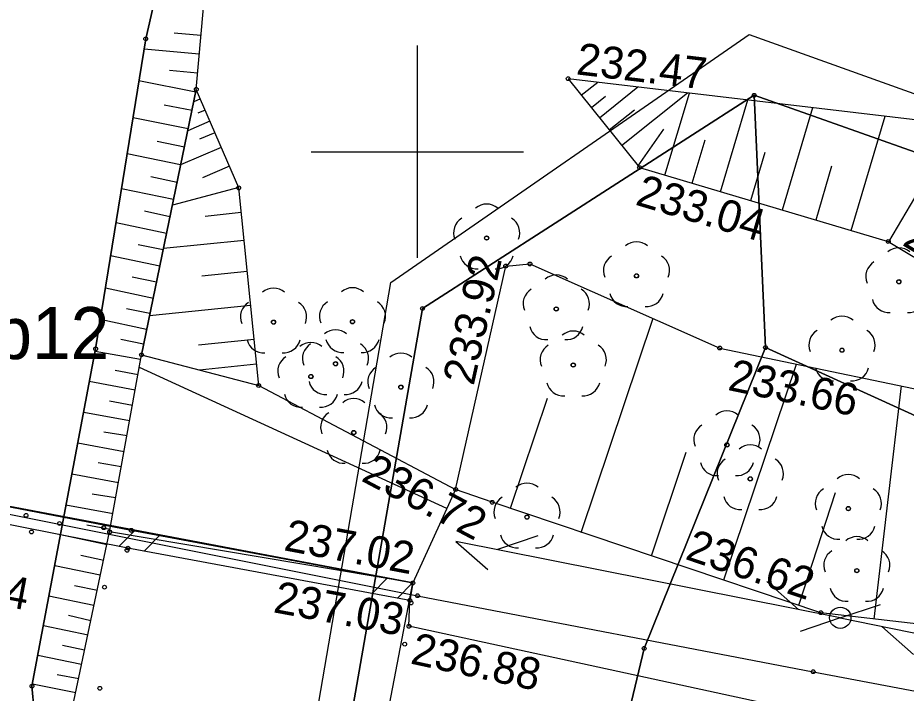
# Model space of a CAD drawing. Extents: x 6596400 to 6597200, y 5539751 to 5540251.
# Drawn here: x 6596740.59 to 6596761.51, y 5540088.25 to 5540104.16 of the extents above; entities that cross this region are included whole.
import ezdxf

# ---------------------------------------------------------------- set-up
doc = ezdxf.new("R2010")
doc.units = 0
for name, color, linetype in [('000 Inne (niezydentyfikowane)', 7, 'Continuous'), ('140-Punkty robocze', 7, 'Continuous'), ('203-punkt graniczny', 7, 'Continuous'), ('217-kontur klasyfikacyjny', 7, 'Continuous'), ('218-kontur użytku gruntowego', 7, 'Continuous'), ('219-działka ewidencyjna', 7, 'Continuous'), ('bariera ochronna', 7, 'Continuous'), ('drzewo liściaste', 7, 'Continuous'), ('jezdnia', 7, 'Continuous'), ('Linia obszaru zagospodarowania terenu', 7, 'Continuous'), ('most', 7, 'Continuous'), ('Opis obszaru zagospodarowania terenu', 7, 'Continuous'), ('pikieta sztuczna', 7, 'Continuous'), ('pikieta sztuczna-Atr2', 7, 'Continuous'), ('przewód telekomunikacyjny napowietrzny', 7, 'Continuous'), ('skarpa nieumocniona', 7, 'Continuous'), ('skarpa umocniona', 7, 'Continuous'), ('słup przewodów napowietrznych', 7, 'Continuous'), ('woda płynąca', 7, 'Continuous'), ('Wstawianie ramki sekcyjnej z opisem', 7, 'Continuous'), ('ściana oporowa (poligon)', 7, 'Continuous')]:
    doc.layers.add(name, color=color, linetype=linetype)

# ---------------------------------------------------------------- blocks, each defined once
blk = doc.blocks.new('203')
blk.add_circle((0, 0), 0.045)
blk = doc.blocks.new('US15')
blk.add_circle((0, 0), 0.25)
blk = doc.blocks.new('SUTP')
for p, q in [((0, 0), (0.866, 0.5)), ((9.232, 0), (8.366, 0.5)), ((0, 0), (9.232, 0)), ((1.866, -0.5), (1, 0)), ((7.366, -0.5), (8.232, 0))]:
    blk.add_line(p, q)
blk = doc.blocks.new('OP021')
blk.add_circle((0, 0), 0.05)
for centre, start, end in [((0, 0.4), 49.272, 130.728), ((-0.38, 0.124), 121.308, 202.548), ((0.38, 0.124), 337.452, 58.692), ((-0.235, -0.324), 193.221, 274.871), ((0.235, -0.324), 265.129, 346.779)]:
    blk.add_arc(centre, 0.4, start, end)
blk = doc.blocks.new('RAMKA500K')
for p, q in [((350, 98.5), (350, 103.5)), ((347.5, 101), (352.5, 101))]:
    blk.add_line(p, q)
blk = doc.blocks.new('PW01')
blk.add_circle((0, 0), 0.045)
blk = doc.blocks.new('PIKIETA')
blk.add_circle((0, 0), 0.045)

msp = doc.modelspace()

# ---------------------------------------------------------------- linework, layer by layer
at = {"layer": '000 Inne (niezydentyfikowane)'}
for p, q in [((6596753.86, 5540092.04), (6596755.55, 5540097.08)), ((6596757.22, 5540090.92), (6596758.93, 5540096)), ((6596760.76, 5540090), (6596761.4, 5540095.49)), ((6596752.19, 5540092.61), (6596753.06, 5540095.2)), ((6596755.51, 5540091.49), (6596756.33, 5540093.93)), ((6596758.98, 5540090.33), (6596759.85, 5540092.98))]:
    msp.add_line(p, q, dxfattribs=at)
for points in [[(6596744.9, 5540103.74), (6596744.27, 5540103.79)], [(6596744.86, 5540103.3), (6596743.56, 5540103.42)], [(6596744.82, 5540102.85), (6596744.16, 5540102.91)], [(6596744.78, 5540102.4), (6596743.44, 5540102.67)], [(6596753.86, 5540102.33), (6596754.25, 5540102.64)], [(6596754.29, 5540101.8), (6596755.19, 5540102.53)], [(6596754.1, 5540102.04), (6596754.43, 5540102.31)], [(6596754.81, 5540101.15), (6596756.36, 5540102.39)], [(6596755.83, 5540100.45), (6596756.41, 5540102.38)], [(6596744.69, 5540101.97), (6596744.03, 5540102.1)], [(6596744.89, 5540102.25), (6596744.73, 5540102.18)], [(6596757.14, 5540100.06), (6596757.78, 5540102.22)], [(6596745, 5540101.98), (6596744.83, 5540101.91)], [(6596754.52, 5540101.52), (6596755.11, 5540101.99)], [(6596758.6, 5540099.63), (6596759.31, 5540102.04)], [(6596744.6, 5540101.54), (6596743.3, 5540101.8)], [(6596745.11, 5540101.72), (6596744.59, 5540101.49)], [(6596760.22, 5540099.15), (6596761.02, 5540101.84)], [(6596755.2, 5540100.67), (6596755.8, 5540101.53)], [(6596745.23, 5540101.45), (6596744.87, 5540101.3)], [(6596756.47, 5540100.26), (6596756.78, 5540101.28)], [(6596744.51, 5540101.11), (6596743.87, 5540101.24)], [(6596745.38, 5540101.1), (6596744.42, 5540100.69)], [(6596744.42, 5540100.69), (6596743.16, 5540100.95)], [(6596757.85, 5540099.85), (6596758.19, 5540100.99)], [(6596745.57, 5540100.66), (6596744.94, 5540100.39)], [(6596759.39, 5540099.4), (6596759.76, 5540100.67)], [(6596744.34, 5540100.28), (6596743.72, 5540100.41)], [(6596761.1, 5540098.88), (6596761.92, 5540100.26)], [(6596744.25, 5540099.88), (6596743.03, 5540100.13)], [(6596745.79, 5540100.16), (6596744.23, 5540099.74)], [(6596744.17, 5540099.47), (6596743.57, 5540099.6)], [(6596745.85, 5540099.57), (6596745, 5540099.48)], [(6596744.09, 5540099.08), (6596742.9, 5540099.33)], [(6596744.01, 5540098.69), (6596743.42, 5540098.81)], [(6596745.92, 5540098.91), (6596744.02, 5540098.72)], [(6596743.93, 5540098.31), (6596742.77, 5540098.55)], [(6596745.99, 5540098.18), (6596744.92, 5540098.07)], [(6596743.85, 5540097.93), (6596743.28, 5540098.05)], [(6596743.78, 5540097.55), (6596742.65, 5540097.79)], [(6596743.7, 5540097.19), (6596743.15, 5540097.3)], [(6596746.07, 5540097.38), (6596743.69, 5540097.14)], [(6596743.62, 5540096.82), (6596742.53, 5540097.05)], [(6596743.55, 5540096.47), (6596743.01, 5540096.58)], [(6596746.15, 5540096.58), (6596744.84, 5540096.45)], [(6596743.48, 5540096.11), (6596742.41, 5540096.3)], [(6596743.42, 5540095.75), (6596742.88, 5540095.85)], [(6596750.69, 5540092.6), (6596743.45, 5540095.92)], [(6596746.21, 5540096), (6596744.87, 5540095.86)], [(6596743.35, 5540095.39), (6596742.27, 5540095.59)], [(6596743.29, 5540095.03), (6596742.75, 5540095.13)], [(6596743.22, 5540094.67), (6596742.14, 5540094.86)], [(6596743.16, 5540094.31), (6596742.61, 5540094.4)], [(6596743.09, 5540093.94), (6596742, 5540094.14)], [(6596743.02, 5540093.58), (6596742.48, 5540093.68)], [(6596742.96, 5540093.21), (6596741.86, 5540093.41)], [(6596742.89, 5540092.85), (6596742.34, 5540092.94)], [(6596742.83, 5540092.48), (6596741.72, 5540092.68)], [(6596742.76, 5540092.11), (6596742.21, 5540092.21)], [(6596742.69, 5540091.75), (6596741.59, 5540091.98)], [(6596742.61, 5540091.38), (6596742.07, 5540091.5)], [(6596742.53, 5540091.03), (6596741.46, 5540091.25)], [(6596742.46, 5540090.67), (6596741.92, 5540090.78)], [(6596742.38, 5540090.32), (6596741.32, 5540090.54)], [(6596742.31, 5540089.96), (6596741.78, 5540090.08)], [(6596742.24, 5540089.62), (6596741.19, 5540089.84)], [(6596742.16, 5540089.27), (6596741.64, 5540089.38)], [(6596742.09, 5540088.93), (6596741.06, 5540089.14)], [(6596742.02, 5540088.59), (6596741.51, 5540088.69)], [(6596741.95, 5540088.26), (6596740.93, 5540088.47)]]:
    msp.add_lwpolyline(points, dxfattribs=at)
at = {"layer": '217-kontur klasyfikacyjny'}
for points in [[(6596776.03, 5540095.93), (6596757.93, 5540102.33)], [(6596757.93, 5540102.33), (6596758.2, 5540096.39)], [(6596758.2, 5540096.39), (6596777.15, 5540087.76)]]:
    msp.add_lwpolyline(points, dxfattribs=at)
at = {"layer": '218-kontur użytku gruntowego'}
for points in [[(6596750.12, 5540097.31), (6596757.93, 5540102.33)], [(6596757.93, 5540102.33), (6596750.12, 5540097.31)], [(6596757.93, 5540102.33), (6596776.03, 5540095.93)], [(6596758.2, 5540096.39), (6596757.93, 5540102.33)], [(6596776.03, 5540095.93), (6596757.93, 5540102.33)], [(6596757.93, 5540102.33), (6596758.2, 5540096.39)], [(6596745.91, 5540073.23), (6596750.12, 5540097.31)], [(6596750.12, 5540097.31), (6596745.91, 5540073.23)], [(6596755.34, 5540089.31), (6596758.2, 5540096.39)], [(6596758.2, 5540096.39), (6596755.34, 5540089.31)], [(6596758.2, 5540096.39), (6596777.15, 5540087.76)], [(6596777.15, 5540087.76), (6596758.2, 5540096.39)], [(6596753.14, 5540080.12), (6596755.34, 5540089.31)], [(6596755.34, 5540089.31), (6596753.14, 5540080.12)]]:
    msp.add_lwpolyline(points, dxfattribs=at)
at = {"layer": '219-działka ewidencyjna'}
for points in [[(6596750.12, 5540097.31), (6596757.93, 5540102.33)], [(6596758.2, 5540096.39), (6596757.93, 5540102.33)], [(6596776.03, 5540095.93), (6596757.93, 5540102.33)], [(6596745.91, 5540073.23), (6596750.12, 5540097.31)], [(6596755.34, 5540089.31), (6596758.2, 5540096.39)], [(6596758.2, 5540096.39), (6596777.15, 5540087.76)], [(6596753.14, 5540080.12), (6596755.34, 5540089.31)]]:
    msp.add_lwpolyline(points, dxfattribs=at)
at = {"layer": 'bariera ochronna'}
msp.add_lwpolyline([(6596724.82, 5540100.27), (6596724.21, 5540095.84), (6596728.33, 5540094.88), (6596750, 5540090.55), (6596759.32, 5540088.76), (6596768.42, 5540087.04), (6596777.66, 5540085.28), (6596786.8, 5540083.5), (6596789.01, 5540083.12), (6596792.87, 5540082.26), (6596795.36, 5540081.78), (6596800.78, 5540080.9), (6596809.14, 5540079.91)], dxfattribs=at)
at = {"layer": 'jezdnia'}
msp.add_lwpolyline([(6596828.719, 5540062.578), (6596825.42, 5540065.32), (6596821.78, 5540067.97), (6596818.46, 5540070.24), (6596813.26, 5540073.35), (6596810.44, 5540074.77), (6596805.94, 5540076.86), (6596804.14, 5540077.61), (6596801.52, 5540078.62), (6596798.28, 5540079.76), (6596795.16, 5540080.71), (6596792.67, 5540081.35), (6596788.77, 5540082.14), (6596786.6, 5540082.54), (6596777.46, 5540084.34), (6596768.21, 5540086.12), (6596759.17, 5540087.8), (6596749.8, 5540089.83), (6596749.82, 5540090.44), (6596743.18, 5540091.67), (6596739.76, 5540092.34), (6596735.83, 5540093.08), (6596728.26, 5540094.5), (6596723.35, 5540095.14)], dxfattribs=at)
at = {"layer": 'Linia obszaru zagospodarowania terenu'}
msp.add_lwpolyline([(6596746.77, 5540082.74), (6596749.37, 5540097.92), (6596757.81, 5540103.76), (6596775.58, 5540097.4), (6596790.99, 5540107), (6596791.128, 5540108.731)], dxfattribs=at)
at = {"layer": 'most'}
msp.add_lwpolyline([(6596728.62, 5540094.88), (6596726.85, 5540087.53), (6596748.43, 5540083.24), (6596749.89, 5540090.85)], close=True, dxfattribs=at)
at = {"layer": 'skarpa nieumocniona'}
for points in [[(6596742.42, 5540096.36), (6596740.92, 5540088.42), (6596741.25, 5540084.94), (6596741.25, 5540084.94), (6596742.75, 5540092.05), (6596743.5, 5540096.22), (6596744.79, 5540102.47), (6596745.19, 5540106.93), (6596748.55, 5540109.04), (6596750.9, 5540110.05), (6596759.79, 5540109.57), (6596764.72, 5540107.7), (6596768.41, 5540103.97), (6596769.44, 5540104.84), (6596765.11, 5540108.34), (6596759.95, 5540110.31), (6596750.9, 5540111.08), (6596747.66, 5540110.25), (6596744.49, 5540107.55), (6596743.6, 5540103.66)], [(6596742.42, 5540096.36), (6596740.92, 5540088.42), (6596741.25, 5540084.94), (6596741.25, 5540084.94), (6596742.75, 5540092.05), (6596743.5, 5540096.22), (6596744.79, 5540102.47), (6596745.19, 5540106.93), (6596748.55, 5540109.04), (6596750.9, 5540110.05), (6596759.79, 5540109.57), (6596764.72, 5540107.7), (6596768.41, 5540103.97), (6596769.44, 5540104.84), (6596765.11, 5540108.34), (6596759.95, 5540110.31), (6596750.9, 5540111.08), (6596747.66, 5540110.25), (6596744.49, 5540107.55), (6596743.6, 5540103.66)], [(6596769.64, 5540093.77), (6596768.56, 5540097.18), (6596762.92, 5540101.61), (6596753.55, 5540102.72), (6596755.23, 5540100.63), (6596761.09, 5540098.89)], [(6596769.64, 5540093.77), (6596768.56, 5540097.18), (6596762.92, 5540101.61), (6596753.55, 5540102.72), (6596755.23, 5540100.63), (6596761.09, 5540098.89)], [(6596743.5, 5540096.22), (6596746.26, 5540095.5), (6596745.79, 5540100.15), (6596744.79, 5540102.47)], [(6596743.5, 5540096.22), (6596746.26, 5540095.5), (6596745.79, 5540100.15), (6596744.79, 5540102.47)]]:
    msp.add_lwpolyline(points, close=True, dxfattribs=at)
msp.add_lwpolyline([(6596792.35, 5540085.37), (6596783.74, 5540087.08), (6596778.16, 5540087.27), (6596768.82, 5540089.13), (6596765.41, 5540089.46), (6596759.5, 5540090.15), (6596751.76, 5540092.75), (6596750.9, 5540093.05), (6596752.08, 5540098.31), (6596752.65, 5540098.36), (6596757.12, 5540096.38), (6596769.64, 5540093.77), (6596783.42, 5540094.18), (6596788.65, 5540093.09)], dxfattribs=at)
msp.add_lwpolyline([(6596792.35, 5540085.37), (6596783.74, 5540087.08), (6596778.16, 5540087.27), (6596768.82, 5540089.13), (6596765.41, 5540089.46), (6596759.5, 5540090.15), (6596751.76, 5540092.75), (6596750.9, 5540093.05), (6596752.08, 5540098.31), (6596752.65, 5540098.36), (6596757.12, 5540096.38), (6596769.64, 5540093.77), (6596783.42, 5540094.18), (6596788.65, 5540093.09)], dxfattribs=at)
at = {"layer": 'skarpa umocniona'}
msp.add_lwpolyline([(6596743.5, 5540096.22), (6596746.26, 5540095.5), (6596750.9, 5540093.05), (6596749.89, 5540090.85), (6596742.75, 5540092.05)], close=True, dxfattribs=at)
msp.add_lwpolyline([(6596743.5, 5540096.22), (6596746.26, 5540095.5), (6596750.9, 5540093.05), (6596749.89, 5540090.85), (6596742.75, 5540092.05)], close=True, dxfattribs=at)
at = {"layer": 'woda płynąca'}
msp.add_lwpolyline([(6596746.88, 5540042.02), (6596743.2, 5540046.89), (6596742.01, 5540050.53), (6596741.65, 5540054.82), (6596742.47, 5540061.97), (6596743.25, 5540066.3), (6596741.68, 5540074.92), (6596740.68, 5540078.45), (6596740.72, 5540079.85), (6596740.91, 5540084.82), (6596741.25, 5540084.94), (6596740.92, 5540088.42), (6596742.42, 5540096.36), (6596743.6, 5540103.66), (6596744.49, 5540107.55), (6596747.66, 5540110.25), (6596750.9, 5540111.08), (6596759.95, 5540110.31), (6596765.11, 5540108.34), (6596769.44, 5540104.84), (6596775.99, 5540100.07), (6596783.39, 5540096.06), (6596790.43, 5540094.51)], dxfattribs=at)
at = {"layer": 'ściana oporowa (poligon)'}
msp.add_lwpolyline([(6596749.89, 5540090.85), (6596749.82, 5540090.44), (6596743.18, 5540091.67), (6596739.76, 5540092.34), (6596735.83, 5540093.08), (6596728.26, 5540094.5), (6596728.62, 5540094.88), (6596735.9, 5540093.49), (6596739.82, 5540092.75), (6596743.26, 5540092.09)], close=True, dxfattribs=at)
msp.add_lwpolyline([(6596749.89, 5540090.85), (6596749.82, 5540090.44), (6596743.18, 5540091.67), (6596739.76, 5540092.34), (6596735.83, 5540093.08), (6596728.26, 5540094.5), (6596728.62, 5540094.88), (6596735.9, 5540093.49), (6596739.82, 5540092.75), (6596743.26, 5540092.09)], close=True, dxfattribs=at)
for points in [[(6596742.967, 5540091.712), (6596743.332, 5540092.077)], [(6596743.561, 5540091.599), (6596743.927, 5540091.965)], [(6596748.931, 5540090.605), (6596749.289, 5540090.962)], [(6596749.527, 5540090.494), (6596749.884, 5540090.851)]]:
    msp.add_lwpolyline(points, dxfattribs=at)

# ---------------------------------------------------------------- block references
at = {"layer": '140-Punkty robocze'}
for p in [(6596743.6, 5540103.66), (6596753.55, 5540102.72), (6596744.79, 5540102.47), (6596755.23, 5540100.63), (6596745.79, 5540100.15), (6596751.63, 5540098.97), (6596761.09, 5540098.89), (6596752.65, 5540098.36), (6596755.16, 5540098.08), (6596761.34, 5540097.94), (6596753.27, 5540097.3), (6596746.61, 5540096.99), (6596748.47, 5540097), (6596742.42, 5540096.36), (6596743.5, 5540096.22), (6596757.12, 5540096.38), (6596760, 5540096.33), (6596748.07, 5540096.01), (6596753.67, 5540095.98), (6596747.49, 5540095.71), (6596746.26, 5540095.5), (6596749.61, 5540095.46), (6596748.5, 5540094.39), (6596757.29, 5540094.1), (6596757.84, 5540093.3), (6596751.76, 5540092.75), (6596740.78, 5540092.44), (6596760.15, 5540092.6), (6596741.57, 5540092.25), (6596752.58, 5540092.4), (6596740.91, 5540092.05), (6596742.61, 5540092.15), (6596742.75, 5540092.05), (6596743.26, 5540092.09), (6596743.16, 5540091.62), (6596743.18, 5540091.67), (6596760.35, 5540091.14), (6596742.63, 5540090.75), (6596750, 5540090.55), (6596749.85, 5540090.38), (6596759.5, 5540090.15), (6596749.7, 5540089.41), (6596759.32, 5540088.76), (6596740.92, 5540088.42), (6596742.52, 5540088.37)]:
    msp.add_blockref('PIKIETA', p, dxfattribs=at)
at = {"layer": '203-punkt graniczny'}
for p in [(6596757.93, 5540102.33), (6596750.12, 5540097.31), (6596758.2, 5540096.39), (6596755.34, 5540089.31)]:
    msp.add_blockref('203', p, dxfattribs=at)
at = {"layer": 'drzewo liściaste'}
for p in [(6596751.63, 5540098.97), (6596755.16, 5540098.08), (6596761.34, 5540097.94), (6596753.27, 5540097.3), (6596746.61, 5540096.99), (6596748.47, 5540097), (6596760, 5540096.33), (6596748.07, 5540096.01), (6596753.67, 5540095.98), (6596747.49, 5540095.71), (6596749.61, 5540095.46), (6596748.5, 5540094.39), (6596757.29, 5540094.1), (6596757.84, 5540093.3), (6596760.15, 5540092.6), (6596752.58, 5540092.4), (6596760.35, 5540091.14)]:
    msp.add_blockref('OP021', p, dxfattribs=at)
at = {"layer": 'pikieta sztuczna'}
for p in [(6596753.55, 5540102.72), (6596755.23, 5540100.63), (6596761.09, 5540098.89), (6596752.08, 5540098.31), (6596757.12, 5540096.38), (6596750.9, 5540093.05), (6596749.89, 5540090.85), (6596749.82, 5540090.44), (6596759.5, 5540090.15), (6596749.8, 5540089.83), (6596740.92, 5540088.42)]:
    msp.add_blockref('PW01', p, dxfattribs=at)
at = {"layer": 'przewód telekomunikacyjny napowietrzny'}
for rotation in [168.764, -11.666000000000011]:
    msp.add_blockref('SUTP', (6596759.96, 5540090.03), dxfattribs=dict(at, rotation=rotation))
at = {"layer": 'słup przewodów napowietrznych'}
msp.add_blockref('US15', (6596759.96, 5540090.03), dxfattribs=at)
at = {"layer": 'Wstawianie ramki sekcyjnej z opisem'}
msp.add_blockref('RAMKA500K', (6596400, 5540000), dxfattribs=at)

# ---------------------------------------------------------------- texts
at = {"layer": 'Opis obszaru zagospodarowania terenu'}
msp.add_text('WSp12', height=1.225, dxfattribs=at).set_placement((6596737.37, 5540096.12))
at = {"layer": 'pikieta sztuczna-Atr2'}
for s, rotation, p in [('232.47', 353.244, (6596753.722, 5540102.825)), ('233.04', 343.462, (6596755.107, 5540099.761)), ('233.54', 329.086, (6596761.395, 5540098.817)), ('233.92', 77.356, (6596751.322, 5540095.476)), ('233.66', 348.224, (6596757.287, 5540095.396)), ('236.72', 332.165, (6596748.65, 5540093.267)), ('237.02', 349.271, (6596746.83, 5540091.623)), ('236.62', 341.432, (6596756.281, 5540091.419)), ('236.94', 349.336, (6596737.761, 5540090.773)), ('237.03', 349.505, (6596746.583, 5540090.163)), ('236.88', 347.776, (6596749.811, 5540088.957))]:
    msp.add_text(s, height=0.75, rotation=rotation, dxfattribs=at).set_placement(p)

doc.saveas('drawing.dxf')
